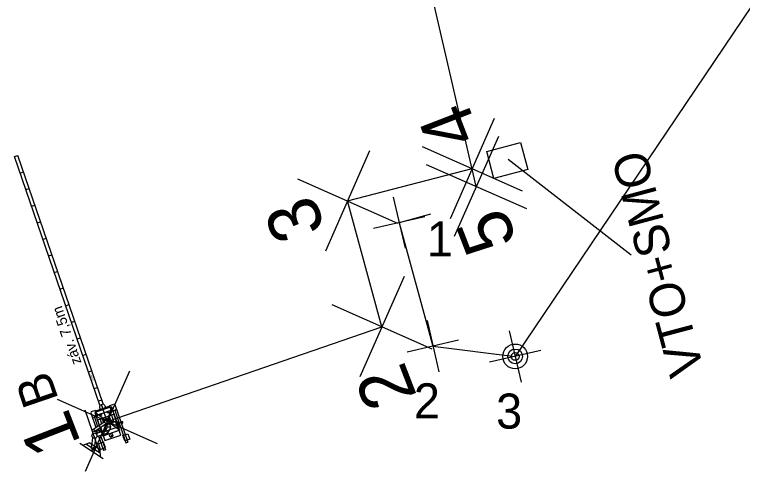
# Model space of a CAD drawing. Extents: x -553584 to -553445, y -1067272 to -1066959.
# Drawn here: x -553518.67 to -553497.88, y -1066993.58 to -1066980.54 of the extents above; entities that cross this region are included whole.
import ezdxf

# ---------------------------------------------------------------- set-up
doc = ezdxf.new("R2010")
doc.units = 0
for name, color, linetype in [('Body', 7, 'Continuous'), ('Default', 7, 'Continuous'), ('Křížky', 7, 'Continuous'), ('Lomové body_cisla', 7, 'Continuous'), ('Lomové body_krizky', 7, 'Continuous'), ('Nová kabelizace', 7, 'Continuous'), ('nové prvky ZZ', 7, 'Continuous'), ('trasa_NN_popisky', 7, 'Continuous'), ('trasa_NN_uzemneni', 7, 'Continuous')]:
    doc.layers.add(name, color=color, linetype=linetype)

# ---------------------------------------------------------------- blocks, each defined once
blk = doc.blocks.new('Křížek')
at = {"layer": 'Křížky'}
for p, q in [((8.84, -8.84), (-8.84, 8.84)), ((8.84, -8.84), (-8.84, 8.84)), ((8.84, -8.84), (-8.84, 8.84)), ((8.84, 8.84), (-8.84, -8.84))]:
    blk.add_line(p, q, dxfattribs=at)
blk = doc.blocks.new('POINT_DISPLAY')
at = {"layer": 'Default'}
blk.add_line((0, 0), (0, 0), dxfattribs=at)
blk = doc.blocks.new('C04927')
at = {"layer": 'Lomové body_krizky'}
for p, q in [((-0.002121, -0.002121), (0.002121, 0.002121)), ((0.002121, -0.002121), (-0.002121, 0.002121))]:
    blk.add_line(p, q, dxfattribs=at)
blk.add_blockref('POINT_DISPLAY', (0, 0), dxfattribs=at)

msp = doc.modelspace()

# ---------------------------------------------------------------- linework, layer by layer
at = {"layer": 'Nová kabelizace'}
for p, q in [((-553505.478, -1066985.448), (-553507.017, -1066978.813)), ((-553509.157, -1066985.86), (-553505.596, -1066984.938)), ((-553508.173, -1066989.45), (-553509.157, -1066985.86)), ((-553516.02, -1066992.15), (-553508.173, -1066989.45))]:
    msp.add_line(p, q, dxfattribs=at)
at = {"layer": 'nové prvky ZZ'}
for p, q in [((-553505.18, -1066984.448), (-553504.213, -1066984.191)), ((-553504.213, -1066984.191), (-553504.008, -1066984.964)), ((-553518.666, -1066984.593), (-553518.572, -1066984.56)), ((-553516.232, -1066991.687), (-553518.666, -1066984.593)), ((-553516.138, -1066991.654), (-553518.572, -1066984.56)), ((-553504.568, -1066984.671), (-553501.059, -1066987.4)), ((-553518.504, -1066985.066), (-553518.41, -1066985.033)), ((-553518.341, -1066985.538), (-553518.248, -1066985.506)), ((-553518.179, -1066986.011), (-553518.085, -1066985.979)), ((-553518.017, -1066986.484), (-553517.923, -1066986.452)), ((-553517.855, -1066986.957), (-553517.761, -1066986.925)), ((-553517.692, -1066987.43), (-553517.598, -1066987.398)), ((-553517.53, -1066987.903), (-553517.436, -1066987.871)), ((-553517.368, -1066988.376), (-553517.274, -1066988.344)), ((-553517.205, -1066988.849), (-553517.112, -1066988.817)), ((-553517.043, -1066989.322), (-553516.949, -1066989.29)), ((-553516.881, -1066989.795), (-553516.787, -1066989.763)), ((-553516.719, -1066990.268), (-553516.625, -1066990.236)), ((-553516.556, -1066990.741), (-553516.462, -1066990.708)), ((-553516.394, -1066991.214), (-553516.3, -1066991.181)), ((-553516.176, -1066991.542), (-553516.27, -1066991.574)), ((-553515.895, -1066991.731), (-553516.377, -1066991.897)), ((-553516.232, -1066991.687), (-553516.138, -1066991.654)), ((-553516.222, -1066991.814), (-553516.065, -1066991.76)), ((-553516.02, -1066992.15), (-553516.185, -1066991.67)), ((-553515.895, -1066991.731), (-553516.145, -1066992.568)), ((-553515.946, -1066991.701), (-553515.827, -1066991.66)), ((-553515.941, -1066991.717), (-553515.946, -1066991.701)), ((-553515.895, -1066991.731), (-553515.664, -1066992.402)), ((-553515.827, -1066991.66), (-553515.798, -1066991.673)), ((-553515.798, -1066991.673), (-553515.432, -1066992.74)), ((-553515.772, -1066991.822), (-553515.757, -1066991.793)), ((-553516.241, -1066993.022), (-553516.65, -1066991.83)), ((-553516.476, -1066991.883), (-553516.491, -1066991.911)), ((-553516.491, -1066991.911), (-553516.348, -1066992.329)), ((-553516.357, -1066991.842), (-553516.476, -1066991.883)), ((-553516.302, -1066992.003), (-553516.421, -1066992.044)), ((-553516.377, -1066991.897), (-553516.145, -1066992.568)), ((-553515.664, -1066992.402), (-553516.377, -1066991.897)), ((-553516.352, -1066991.858), (-553516.357, -1066991.842)), ((-553516.313, -1066991.97), (-553516.302, -1066992.003)), ((-553515.899, -1066991.978), (-553516.224, -1066992.09)), ((-553515.902, -1066991.829), (-553515.891, -1066991.862)), ((-553515.894, -1066991.977), (-553515.899, -1066991.978)), ((-553515.899, -1066991.978), (-553515.833, -1066992.169)), ((-553515.826, -1066991.948), (-553515.895, -1066991.972)), ((-553515.895, -1066991.972), (-553515.894, -1066991.977)), ((-553515.891, -1066991.862), (-553515.772, -1066991.822)), ((-553515.748, -1066992.173), (-553515.826, -1066991.948)), ((-553515.806, -1066991.833), (-553515.488, -1066992.759)), ((-553516.421, -1066992.044), (-553516.45, -1066992.031)), ((-553516.433, -1066992.387), (-553516.092, -1066992.157)), ((-553516.393, -1066992.443), (-553516.052, -1066992.215)), ((-553516.387, -1066992.033), (-553516.297, -1066992.295)), ((-553516.3, -1066992.111), (-553516.23, -1066992.087)), ((-553516.3, -1066992.111), (-553516.248, -1066992.262)), ((-553516.23, -1066992.087), (-553516.228, -1066992.091)), ((-553516.228, -1066992.091), (-553516.224, -1066992.09)), ((-553516.224, -1066992.09), (-553516.18, -1066992.216)), ((-553516.106, -1066992.104), (-553516.125, -1066992.116)), ((-553516.125, -1066992.116), (-553516.111, -1066992.136)), ((-553516.106, -1066992.166), (-553516.113, -1066992.146)), ((-553516.111, -1066992.136), (-553516.093, -1066992.124)), ((-553516.096, -1066992.159), (-553516.102, -1066992.142)), ((-553516.06, -1066992.081), (-553516.095, -1066992.103)), ((-553516.077, -1066992.105), (-553516.089, -1066992.113)), ((-553516.038, -1066992.237), (-553516.045, -1066992.218)), ((-553516.025, -1066992.152), (-553516.015, -1066992.148)), ((-553516.022, -1066992.145), (-553516.019, -1066992.155)), ((-553516.001, -1066992.22), (-553516.012, -1066992.228)), ((-553515.97, -1066992.211), (-553516.006, -1066992.237)), ((-553515.917, -1066992.32), (-553515.958, -1066992.2)), ((-553515.792, -1066992.155), (-553515.954, -1066992.211)), ((-553515.928, -1066992.156), (-553515.951, -1066992.09)), ((-553515.789, -1066992.166), (-553515.951, -1066992.221)), ((-553515.918, -1066992.148), (-553515.939, -1066992.087)), ((-553515.897, -1066992.14), (-553515.93, -1066992.151)), ((-553515.894, -1066992.151), (-553515.92, -1066992.16)), ((-553515.888, -1066992.141), (-553515.897, -1066992.14)), ((-553515.885, -1066992.151), (-553515.894, -1066992.151)), ((-553515.878, -1066992.146), (-553515.888, -1066992.141)), ((-553515.874, -1066992.183), (-553515.885, -1066992.151)), ((-553515.872, -1066992.153), (-553515.878, -1066992.146)), ((-553515.863, -1066992.179), (-553515.872, -1066992.153)), ((-553515.774, -1066992.155), (-553515.792, -1066992.155)), ((-553515.777, -1066992.17), (-553515.789, -1066992.166)), ((-553515.726, -1066992.317), (-553515.777, -1066992.17)), ((-553515.763, -1066992.169), (-553515.774, -1066992.155)), ((-553515.713, -1066992.312), (-553515.763, -1066992.169)), ((-553515.69, -1066992.251), (-553515.712, -1066992.189)), ((-553515.682, -1066992.193), (-553515.645, -1066992.18)), ((-553515.645, -1066992.18), (-553515.636, -1066992.18)), ((-553515.636, -1066992.18), (-553515.622, -1066992.185)), ((-553515.586, -1066992.162), (-553515.597, -1066992.166)), ((-553515.584, -1066992.167), (-553515.586, -1066992.162)), ((-553515.574, -1066992.195), (-553515.586, -1066992.199)), ((-553515.577, -1066992.164), (-553515.584, -1066992.167)), ((-553515.569, -1066992.188), (-553515.577, -1066992.164)), ((-553515.569, -1066992.188), (-553515.576, -1066992.191)), ((-553515.576, -1066992.191), (-553515.574, -1066992.195)), ((-553516.364, -1066992.434), (-553516.357, -1066992.432)), ((-553516.359, -1066992.428), (-553516.347, -1066992.424)), ((-553516.357, -1066992.432), (-553516.359, -1066992.428)), ((-553516.056, -1066992.404), (-553516.342, -1066992.502)), ((-553516.324, -1066992.397), (-553516.294, -1066992.486)), ((-553516.308, -1066992.41), (-553516.315, -1066992.423)), ((-553516.301, -1066992.405), (-553516.308, -1066992.41)), ((-553516.264, -1066992.392), (-553516.301, -1066992.405)), ((-553516.274, -1066992.363), (-553516.238, -1066992.467)), ((-553516.212, -1066992.323), (-553516.218, -1066992.334)), ((-553516.183, -1066992.409), (-553516.212, -1066992.322)), ((-553516.16, -1066992.44), (-553516.203, -1066992.316)), ((-553516.034, -1066992.25), (-553516.178, -1066992.299)), ((-553515.663, -1066992.402), (-553516.145, -1066992.568)), ((-553515.72, -1066992.422), (-553516.145, -1066992.568)), ((-553516.039, -1066992.24), (-553516.142, -1066992.275)), ((-553516.056, -1066992.404), (-553516.013, -1066992.312)), ((-553515.995, -1066992.476), (-553516.056, -1066992.404)), ((-553516.04, -1066992.238), (-553516.024, -1066992.227)), ((-553516.027, -1066992.259), (-553516.04, -1066992.238)), ((-553516.013, -1066992.312), (-553516.035, -1066992.245)), ((-553516.01, -1066992.247), (-553516.027, -1066992.259)), ((-553515.917, -1066992.32), (-553516.013, -1066992.312)), ((-553515.995, -1066992.476), (-553515.917, -1066992.32)), ((-553516.464, -1066992.923), (-553516.429, -1066992.616)), ((-553516.385, -1066992.933), (-553516.349, -1066992.625)), ((-553516.356, -1066992.458), (-553516.364, -1066992.434)), ((-553516.356, -1066992.458), (-553516.349, -1066992.456)), ((-553516.349, -1066992.456), (-553516.347, -1066992.46)), ((-553516.347, -1066992.46), (-553516.336, -1066992.456)), ((-553516.316, -1066992.586), (-553515.995, -1066992.476)), ((-553516.265, -1066992.569), (-553516.125, -1066992.978)), ((-553516.21, -1066992.549), (-553516.069, -1066992.958)), ((-553515.86, -1066992.547), (-553515.857, -1066992.546)), ((-553516.132, -1066993.216), (-553516.803, -1066992.78)), ((-553516.719, -1066992.834), (-553516.533, -1066992.76)), ((-553516.22, -1066993.062), (-553516.626, -1066992.797)), ((-553516.223, -1066992.962), (-553516.533, -1066992.76)), ((-553515.488, -1066992.759), (-553515.432, -1066992.74)), ((-553516.467, -1066992.998), (-553516.378, -1066992.861)), ((-553516.414, -1066992.928), (-553516.431, -1066992.931)), ((-553516.424, -1066992.921), (-553516.422, -1066992.938)), ((-553516.216, -1066993.162), (-553516.223, -1066992.962)), ((-553516.069, -1066992.958), (-553516.125, -1066992.978))]:
    msp.add_line(p, q, dxfattribs=at)
for points in [[(-553504.008, -1066984.964), (-553504.974, -1066985.221), (-553505.18, -1066984.448)], [(-553516.232, -1066991.687), (-553516.244, -1066991.755), (-553516.223, -1066991.814)], [(-553516.138, -1066991.654), (-553516.086, -1066991.701), (-553516.066, -1066991.76)], [(-553516.202, -1066991.973), (-553516.207, -1066991.974), (-553516.22, -1066991.938), (-553516.192, -1066991.929), (-553516.179, -1066991.965), (-553516.184, -1066991.966)], [(-553516.184, -1066991.966), (-553516.182, -1066991.974), (-553516.2, -1066991.981), (-553516.202, -1066991.973)], [(-553516.004, -1066991.904), (-553516.008, -1066991.906), (-553516.021, -1066991.87), (-553515.993, -1066991.861), (-553515.981, -1066991.897), (-553515.986, -1066991.898)], [(-553515.986, -1066991.898), (-553515.983, -1066991.906), (-553516.001, -1066991.912), (-553516.004, -1066991.904)], [(-553516.109, -1066992.095), (-553516.113, -1066992.085), (-553516.151, -1066992.099), (-553516.135, -1066992.144)], [(-553516.112, -1066992.135), (-553516.145, -1066992.147), (-553516.141, -1066992.156), (-553516.092, -1066992.139)], [(-553516.085, -1066992.118), (-553516.103, -1066992.091), (-553516.111, -1066992.096), (-553516.089, -1066992.128)], [(-553516.09, -1066992.128), (-553516.107, -1066992.134)], [(-553516.016, -1066992.222), (-553515.998, -1066992.25), (-553516.005, -1066992.255), (-553516.027, -1066992.222)], [(-553515.971, -1066992.087), (-553515.934, -1066992.075), (-553515.95, -1066992.03), (-553515.988, -1066992.043), (-553515.974, -1066992.086)], [(-553515.963, -1066992.095), (-553515.923, -1066992.081), (-553515.926, -1066992.072), (-553515.971, -1066992.087), (-553515.971, -1066992.088)], [(-553515.943, -1066992.168), (-553515.942, -1066992.171), (-553515.916, -1066992.162), (-553515.919, -1066992.153), (-553515.942, -1066992.161)], [(-553515.712, -1066992.189), (-553515.72, -1066992.164), (-553515.753, -1066992.175), (-553515.726, -1066992.252)], [(-553515.69, -1066992.251), (-553515.678, -1066992.247), (-553515.7, -1066992.185), (-553515.712, -1066992.189)], [(-553515.617, -1066992.169), (-553515.621, -1066992.157), (-553515.631, -1066992.161), (-553515.609, -1066992.224), (-553515.6, -1066992.221), (-553515.603, -1066992.209)], [(-553515.597, -1066992.166), (-553515.599, -1066992.162), (-553515.617, -1066992.169)], [(-553515.603, -1066992.209), (-553515.585, -1066992.203), (-553515.586, -1066992.199)], [(-553516.347, -1066992.424), (-553516.348, -1066992.419), (-553516.33, -1066992.413)], [(-553516.33, -1066992.413), (-553516.333, -1066992.403)], [(-553516.329, -1066992.4), (-553516.324, -1066992.399), (-553516.302, -1066992.462), (-553516.312, -1066992.465), (-553516.316, -1066992.454)], [(-553516.264, -1066992.357), (-553516.229, -1066992.458), (-553516.24, -1066992.462), (-553516.274, -1066992.363)], [(-553516.218, -1066992.432), (-553516.236, -1066992.438), (-553516.257, -1066992.376), (-553516.24, -1066992.37)], [(-553516.24, -1066992.37), (-553516.248, -1066992.346)], [(-553516.244, -1066992.343), (-553516.217, -1066992.334), (-553516.191, -1066992.412)], [(-553516.21, -1066992.457), (-553516.218, -1066992.432)], [(-553516.187, -1066992.449), (-553516.199, -1066992.414), (-553516.183, -1066992.409), (-553516.171, -1066992.444)], [(-553515.704, -1066992.285), (-553515.682, -1066992.277), (-553515.69, -1066992.251)], [(-553516.316, -1066992.454), (-553516.334, -1066992.46), (-553516.336, -1066992.456)], [(-553515.857, -1066992.546), (-553515.874, -1066992.498), (-553515.968, -1066992.53), (-553515.949, -1066992.584), (-553515.909, -1066992.57)], [(-553515.905, -1066992.583), (-553515.932, -1066992.592), (-553515.928, -1066992.604), (-553515.901, -1066992.594)], [(-553515.901, -1066992.594), (-553515.849, -1066992.577), (-553515.86, -1066992.547), (-553515.911, -1066992.564), (-553515.905, -1066992.583)]]:
    msp.add_lwpolyline(points, dxfattribs=at)
for points in [[(-553515.902, -1066991.829), (-553515.941, -1066991.717), (-553516.352, -1066991.858), (-553516.313, -1066991.97)], [(-553515.958, -1066992.033), (-553515.963, -1066992.017), (-553515.985, -1066992.025), (-553515.98, -1066992.04)], [(-553516.121, -1066992.088), (-553516.126, -1066992.073), (-553516.148, -1066992.081), (-553516.143, -1066992.096)], [(-553515.922, -1066992.164), (-553515.919, -1066992.171), (-553515.936, -1066992.177), (-553515.939, -1066992.17)], [(-553515.658, -1066992.262), (-553515.694, -1066992.16), (-553515.707, -1066992.164), (-553515.672, -1066992.267)], [(-553515.634, -1066992.544), (-553515.713, -1066992.312), (-553516.163, -1066992.467), (-553516.083, -1066992.699)], [(-553515.7, -1066992.298), (-553515.717, -1066992.249), (-553515.733, -1066992.254), (-553515.716, -1066992.303)], [(-553515.521, -1066992.71), (-553515.574, -1066992.555), (-553515.428, -1066992.504), (-553515.375, -1066992.66)], [(-553516.073, -1066992.899), (-553516.126, -1066992.744), (-553516.273, -1066992.794), (-553516.219, -1066992.95)]]:
    msp.add_lwpolyline(points, close=True, dxfattribs=at)
for centre, radius in [((-553516.02, -1066992.15), 0.0725), ((-553516.413, -1066992.415), 0.0347), ((-553516.383, -1066992.561), 0.0716), ((-553516.423, -1066992.929), 0.00856)]:
    msp.add_circle(centre, radius, dxfattribs=at)
for centre, radius, start, end in [((-553516.02, -1066992.15), 0.0795, 309.387, 119.921), ((-553516.424, -1066992.927), 0.0399, 173.2567, 354.9637)]:
    msp.add_arc(centre, radius, start, end, dxfattribs=at)
at = {"layer": 'trasa_NN_popisky'}
msp.add_lwpolyline([(-553456.479, -1066963.507), (-553494.623, -1066975.849), (-553504.368, -1066990.297)], dxfattribs=at)
at = {"layer": 'trasa_NN_uzemneni'}
msp.add_lwpolyline([(-553506.79, -1066986.24), (-553507.681, -1066986.481), (-553506.717, -1066990.005), (-553504.368, -1066990.297)], dxfattribs=at)
for radius in [0.354, 0.211, 0.111]:
    msp.add_circle((-553504.368, -1066990.297), radius, dxfattribs=at)

# ---------------------------------------------------------------- block references
at = {"layer": 'Body', "xscale": 0.12500000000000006, "yscale": 0.125, "rotation": 111.13806774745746}
for p in [(-553505.596, -1066984.938), (-553505.478, -1066985.448), (-553509.157, -1066985.86), (-553508.173, -1066989.45), (-553516.02, -1066992.15)]:
    msp.add_blockref('Křížek', p, dxfattribs=at)
at = {"layer": 'Lomové body_krizky', "xscale": 249.9999999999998, "yscale": 249.99999999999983, "rotation": 147.9190601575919}
for p in [(-553507.681, -1066986.481), (-553506.717, -1066990.005), (-553504.368, -1066990.297)]:
    msp.add_blockref('C04927', p, dxfattribs=at)

# ---------------------------------------------------------------- texts
at = {"layer": 'Default'}
for s, p in [('4', (-553505.362, -1066984.012)), ('3', (-553509.768, -1066986.655)), ('5', (-553504.298, -1066987.009)), ('2', (-553507.164, -1066991.432)), ('1', (-553516.759, -1066992.775))]:
    msp.add_text(s, height=1.5, rotation=111.1381, dxfattribs=at).set_placement(p)
at = {"layer": 'Lomové body_cisla'}
for s, p in [('1', (-553506.891, -1066987.445)), ('2', (-553507.261, -1066992.065)), ('3', (-553504.912, -1066992.357))]:
    msp.add_text(s, height=1, dxfattribs=at).set_placement(p)
at = {"layer": 'nové prvky ZZ'}
for s, height, rotation, p in [('VTO+SMO', 1, 104.9376, (-553498.965, -1066990.707)), ('záv. 7,5m', 0.3, 109.138, (-553516.752, -1066990.475)), ('7,50m', 0.0646, 288.9398, (-553516.526, -1066990.764)), ('B', 1.025, 108.8917, (-553517.4, -1066991.525)), ('265', 0.025, 288.9398, (-553515.996, -1066992.119))]:
    msp.add_text(s, height=height, rotation=rotation, dxfattribs=at).set_placement(p)

doc.saveas('drawing.dxf')
